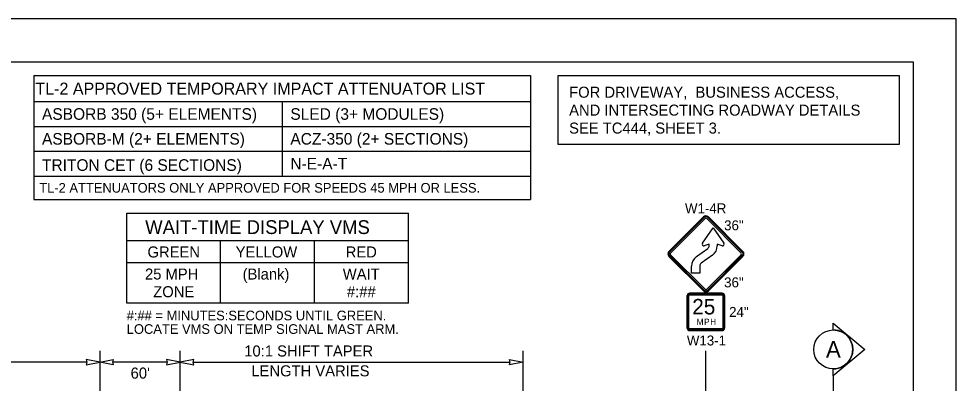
# Model space of a CAD drawing. Extents: x 99976 to 100136, y 99905 to 100011.
# Drawn here: x 100009.27 to 100016.06, y 99948.05 to 99950.69 of the extents above; entities that cross this region are included whole.
import ezdxf

# ---------------------------------------------------------------- set-up
doc = ezdxf.new("R2010")
doc.units = 0
for name, color, linetype in [('SH_GI_PlotLimits', 7, 'Continuous'), ('SH_GI_SheetBorder', 7, 'Continuous'), ('SH_TI_Tables', 7, 'Continuous'), ('SH_TI_WZSectionCut', 7, 'Continuous'), ('TR_SN_ConstructionSigns', 7, 'Continuous'), ('TR_WZ_PortableChangeMessageSign', 7, 'Continuous'), ('TR_WZ_WorkZoneDetails', 7, 'Continuous'), ('TR_WZ_WorkZoneTextCurrent', 7, 'Continuous')]:
    doc.layers.add(name, color=color, linetype=linetype)

msp = doc.modelspace()

# ---------------------------------------------------------------- linework, layer by layer
at = {"layer": 'SH_GI_PlotLimits'}
msp.add_lwpolyline([(99999.0625, 99939.6875), (100016.0625, 99939.6875), (100016.0625, 99950.6875), (99999.0625, 99950.6875)], close=True, dxfattribs=at)
at = {"layer": 'SH_GI_SheetBorder'}
for p, q in [((100000, 99950.375), (100015.75, 99950.375)), ((100015.75, 99950.375), (100015.75, 99940))]:
    msp.add_line(p, q, dxfattribs=at)
at = {"layer": 'SH_TI_Tables'}
for p, q in [((100009.3798, 99950.275), (100009.3798, 99949.377)), ((100009.3798, 99950.275), (100012.9782, 99950.275)), ((100012.9782, 99950.275), (100012.9782, 99949.377)), ((100009.3798, 99950.087), (100012.9782, 99950.087)), ((100011.179, 99950.087), (100011.179, 99949.547)), ((100009.3798, 99949.907), (100012.9782, 99949.907)), ((100009.3798, 99949.727), (100012.9782, 99949.727)), ((100009.3798, 99949.547), (100012.9782, 99949.547)), ((100009.3798, 99949.377), (100012.9782, 99949.377))]:
    msp.add_line(p, q, dxfattribs=at)
msp.add_lwpolyline([(100013.1782, 99950.275), (100015.65, 99950.275), (100015.65, 99949.775), (100013.1782, 99949.775)], close=True, dxfattribs=at)
at = {"layer": 'SH_TI_WZSectionCut'}
for p, q in [((100015.1718, 99948.4317), (100015.1718, 99948.4816)), ((100015.1718, 99948.4816), (100015.4, 99948.2904)), ((100015.4, 99948.2904), (100015.1718, 99948.0993)), ((100015.1718, 99948.0993), (100015.1718, 99948.1492)), ((100015.1718, 99948.0993), (100015.1718, 99946.0193))]:
    msp.add_line(p, q, dxfattribs=at)
msp.add_circle((100015.1718, 99948.2904), 0.1412, dxfattribs=at)
msp.add_arc((100015.1718, 99948.2904), 0.1412, 269.99779, 90.00221, dxfattribs=at)
at = {"layer": 'TR_SN_ConstructionSigns'}
for p, q in [((100014.2311, 99949.2517), (100013.9805, 99949.0011)), ((100014.236, 99949.2467), (100013.9855, 99948.9961)), ((100013.9924, 99948.9892), (100014.243, 99949.2398)), ((100014.2549, 99949.2398), (100014.5055, 99948.9892)), ((100014.5125, 99948.9961), (100014.2619, 99949.2467)), ((100014.5174, 99949.0011), (100014.2669, 99949.2517)), ((100014.2246, 99949.0601), (100014.3021, 99949.173)), ((100014.3021, 99949.173), (100014.3795, 99949.0601)), ((100014.1806, 99948.9631), (100014.262, 99949.0217)), ((100014.2725, 99949.0532), (100014.2366, 99949.0417)), ((100014.2725, 99949.0423), (100014.2725, 99949.0532)), ((100014.3675, 99949.0417), (100014.3316, 99949.0532)), ((100014.3316, 99949.0532), (100014.3316, 99949.0423)), ((100013.9805, 99948.9653), (100014.2311, 99948.7147)), ((100013.9855, 99948.9703), (100014.236, 99948.7197)), ((100014.243, 99948.7267), (100013.9924, 99948.9772)), ((100014.2966, 99948.9738), (100014.2152, 99948.9151)), ((100014.5055, 99948.9772), (100014.2549, 99948.7267)), ((100014.2619, 99948.7197), (100014.5125, 99948.9703)), ((100014.2669, 99948.7147), (100014.5174, 99948.9653)), ((100014.1456, 99948.844), (100014.1456, 99948.8946)), ((100014.2047, 99948.8946), (100014.2047, 99948.844)), ((100014.2047, 99948.844), (100014.1456, 99948.844)), ((100014.114, 99948.4442), (100014.114, 99948.6804)), ((100014.114, 99948.6804), (100014.114, 99948.4442)), ((100014.114, 99948.6804), (100014.114, 99948.4442)), ((100014.1182, 99948.6804), (100014.1182, 99948.4442)), ((100014.1252, 99948.4442), (100014.1252, 99948.6804)), ((100014.1308, 99948.6973), (100014.3671, 99948.6973)), ((100014.3671, 99948.6973), (100014.1308, 99948.6973)), ((100014.3671, 99948.6973), (100014.1308, 99948.6973)), ((100014.3671, 99948.6931), (100014.1308, 99948.6931)), ((100014.1308, 99948.6861), (100014.3671, 99948.6861)), ((100014.3727, 99948.6804), (100014.3727, 99948.4442)), ((100014.3797, 99948.4442), (100014.3797, 99948.6804)), ((100014.384, 99948.6804), (100014.384, 99948.4442)), ((100014.384, 99948.4442), (100014.384, 99948.6804)), ((100014.384, 99948.4442), (100014.384, 99948.6804)), ((100014.3671, 99948.4386), (100014.1308, 99948.4386)), ((100014.1308, 99948.4315), (100014.3671, 99948.4315)), ((100014.3671, 99948.4273), (100014.1308, 99948.4273)), ((100014.1308, 99948.4273), (100014.3671, 99948.4273)), ((100014.1308, 99948.4273), (100014.3671, 99948.4273))]:
    msp.add_line(p, q, dxfattribs=at)
for centre, radius, start, end in [((100014.249, 99949.2338), 0.0253, 45, 135), ((100014.249, 99949.2338), 0.0183, 45, 135), ((100014.249, 99949.2338), 0.00844, 45, 135), ((100013.9984, 99948.9832), 0.0253, 135, 225.00001), ((100014.2346, 99949.0535), 0.012, 146.3859, 280.04666), ((100014.2472, 99949.0423), 0.0253, 305.79396, 0.00002), ((100014.2472, 99949.0423), 0.0844, 305.79396, 0.00002), ((100014.3696, 99949.0535), 0.012, 259.95336, 33.61411), ((100014.4995, 99948.9832), 0.0253, 315.00001, 45.00001), ((100013.9984, 99948.9832), 0.0183, 135, 225.00001), ((100013.9984, 99948.9832), 0.00844, 135, 225.00001), ((100014.23, 99948.8946), 0.0844, 125.79393, 180.00001), ((100014.4995, 99948.9832), 0.00844, 315.00002, 45), ((100014.4995, 99948.9832), 0.0183, 315.00002, 45), ((100014.23, 99948.8946), 0.0253, 125.79393, 180.00001), ((100014.1308, 99948.6804), 0.0169, 90, 180), ((100014.1308, 99948.6804), 0.0169, 90, 180), ((100014.1308, 99948.6804), 0.0169, 90, 180), ((100014.1308, 99948.6804), 0.0127, 90, 180.00001), ((100014.1308, 99948.6804), 0.00562, 90, 180.00001), ((100014.249, 99948.7326), 0.0253, 225.00001, 315.00001), ((100014.249, 99948.7326), 0.0183, 225.00001, 315.00002), ((100014.249, 99948.7326), 0.00844, 225.00001, 315.00002), ((100014.3671, 99948.6804), 0.0169, 0, 90), ((100014.3671, 99948.6804), 0.0169, 0, 90), ((100014.3671, 99948.6804), 0.0169, 0, 90), ((100014.3671, 99948.6804), 0.0127, 0, 90), ((100014.3671, 99948.6804), 0.00562, 0, 90), ((100014.1308, 99948.4442), 0.0169, 180, 270.00001), ((100014.1308, 99948.4442), 0.0169, 180, 270.00001), ((100014.1308, 99948.4442), 0.0169, 180, 270.00001), ((100014.1308, 99948.4442), 0.0127, 180.00001, 270), ((100014.1308, 99948.4442), 0.00562, 180.00001, 270), ((100014.3671, 99948.4442), 0.0169, 270.00001, 0.00001), ((100014.3671, 99948.4442), 0.0169, 270.00001, 0.00001), ((100014.3671, 99948.4442), 0.0127, 270, 0.00001), ((100014.3671, 99948.4442), 0.00562, 270, 0.00001), ((100014.3671, 99948.4442), 0.0169, 270.00001, 0.00001)]:
    msp.add_arc(centre, radius, start, end, dxfattribs=at)
at = {"layer": 'TR_WZ_PortableChangeMessageSign'}
for p, q in [((100010.0535, 99949.277), (100012.0935, 99949.277)), ((100010.0535, 99948.6247), (100010.0535, 99949.277)), ((100012.0935, 99948.6247), (100012.0935, 99949.277)), ((100012.0935, 99949.077), (100010.0535, 99949.077)), ((100010.7335, 99948.6247), (100010.7335, 99949.077)), ((100011.4135, 99948.6247), (100011.4135, 99949.077)), ((100010.7335, 99948.917), (100010.0535, 99948.917)), ((100011.4135, 99948.917), (100010.7335, 99948.917)), ((100012.0935, 99948.917), (100011.4135, 99948.917)), ((100012.0935, 99948.6247), (100010.0535, 99948.6247))]:
    msp.add_line(p, q, dxfattribs=at)
at = {"layer": 'TR_WZ_WorkZoneDetails'}
for p, q in [((100009.8576, 99948.2793), (100009.8576, 99946.9093)), ((100010.4406, 99947.5393), (100010.4406, 99948.2793)), ((100012.9246, 99946.5193), (100012.9246, 99948.2793)), ((100014.2469, 99948.2793), (100014.2469, 99946.8193)), ((100009.7638, 99948.1993), (100008.1013, 99948.1993)), ((100010.3469, 99948.1993), (100009.9513, 99948.1993)), ((100010.5343, 99948.1993), (100012.8309, 99948.1993))]:
    msp.add_line(p, q, dxfattribs=at)
for points in [[(100009.8576, 99948.1993), (100009.7593, 99948.2186), (100009.7638, 99948.1993), (100009.7593, 99948.18)], [(100009.8576, 99948.1993), (100009.9558, 99948.2186), (100009.9513, 99948.1993), (100009.9558, 99948.18)], [(100010.4406, 99948.1993), (100010.3423, 99948.2186), (100010.3469, 99948.1993), (100010.3423, 99948.18)], [(100010.4406, 99948.1993), (100010.5389, 99948.18), (100010.5343, 99948.1993), (100010.5389, 99948.2186)], [(100012.9246, 99948.1993), (100012.8263, 99948.18), (100012.8309, 99948.1993), (100012.8263, 99948.2186)]]:
    msp.add_lwpolyline(points, close=True, dxfattribs=at)

# ---------------------------------------------------------------- texts
at = {"layer": 'SH_TI_Tables'}
for s, height, p in [('TL-2 APPROVED TEMPORARY IMPACT ATTENUATOR LIST', 0.087, (100009.3918, 99950.1375)), ('ASBORB 350 (5+ ELEMENTS)', 0.084, (100009.4398, 99949.955)), ('SLED (3+ MODULES)', 0.084, (100011.239, 99949.955)), ('ASBORB-M (2+ ELEMENTS)', 0.084, (100009.4398, 99949.775)), ('ACZ-350 (2+ SECTIONS)', 0.084, (100011.239, 99949.775)), ('TRITON CET (6 SECTIONS)', 0.084, (100009.4398, 99949.585)), ('N-E-A-T', 0.084, (100011.239, 99949.595)), ('TL-2 ATTENUATORS ONLY APPROVED FOR SPEEDS 45 MPH OR LESS.', 0.07, (100009.4198, 99949.427))]:
    msp.add_text(s, height=height, dxfattribs=at).set_placement(p)
for s, p in [('FOR DRIVEWAY,  BUSINESS ACCESS, ', (100013.2582, 99950.115)), ('AND INTERSECTING ROADWAY DETAILS', (100013.2582, 99949.985)), ('SEE TC444, SHEET 3.', (100013.2582, 99949.855))]:
    msp.add_text(s, height=0.08, rotation=360, dxfattribs=at).set_placement(p)
at = {"layer": 'SH_TI_WZSectionCut'}
msp.add_text('A', height=0.12, rotation=359.99005, dxfattribs=at).set_placement((100015.1189, 99948.2313))
at = {"layer": 'TR_SN_ConstructionSigns'}
for s, height, p in [('W1-4R', 0.072, (100014.0975, 99949.2771)), ('25', 0.1125, (100014.15, 99948.544)), ('M', 0.045, (100014.1817, 99948.4681)), ('P', 0.045, (100014.2357, 99948.4681)), ('H', 0.045, (100014.2798, 99948.4681))]:
    msp.add_text(s, height=height, dxfattribs=at).set_placement(p)
for s, p in [('36"', (100014.381, 99949.154)), ('36"', (100014.381, 99948.7404)), ('24"', (100014.4172, 99948.5263)), ('W13-1', (100014.1111, 99948.3193))]:
    msp.add_text(s, height=0.072, rotation=360, dxfattribs=at).set_placement(p)
at = {"layer": 'TR_WZ_PortableChangeMessageSign'}
for s, height, p in [('WAIT-TIME DISPLAY VMS', 0.1, (100010.1873, 99949.127)), ('GREEN', 0.08, (100010.2041, 99948.957)), ('YELLOW', 0.08, (100010.8426, 99948.957)), ('RED', 0.08, (100011.6396, 99948.957)), ('25 MPH', 0.08, (100010.1859, 99948.797)), ('(Blank)', 0.08, (100010.8931, 99948.797)), ('WAIT', 0.08, (100011.6185, 99948.797)), ('ZONE', 0.08, (100010.2456, 99948.669)), ('#:##', 0.08, (100011.6486, 99948.669)), ('#:## = MINUTES:SECONDS UNTIL GREEN.', 0.07, (100010.0535, 99948.5013)), ('LOCATE VMS ON TEMP SIGNAL MAST ARM.', 0.07, (100010.0535, 99948.4033))]:
    msp.add_text(s, height=height, rotation=360, dxfattribs=at).set_placement(p)
at = {"layer": 'TR_WZ_WorkZoneTextCurrent'}
for s, p in [('10:1 SHIFT TAPER', (100010.9051, 99948.2393)), ("60'", (100010.0819, 99948.0791)), ('LENGTH VARIES', (100010.9564, 99948.0953))]:
    msp.add_text(s, height=0.08, dxfattribs=at).set_placement(p)

doc.saveas('drawing.dxf')
